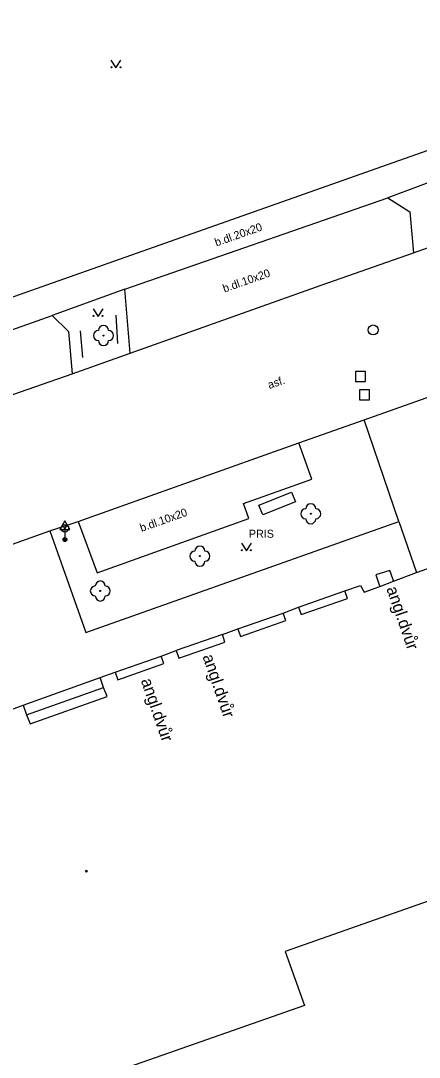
# Model space of a CAD drawing. Extents: x -599770 to -598493, y -1162076 to -1159209.
# Drawn here: x -599035.5 to -599015.6, y -1159443 to -1159391.2 of the extents above; entities that cross this region are included whole.
import ezdxf

# ---------------------------------------------------------------- set-up
doc = ezdxf.new("R2010")
doc.units = 0
doc.layers.add('Podklad', color=7, linetype='Continuous')

msp = doc.modelspace()

# ---------------------------------------------------------------- linework, layer by layer
at = {"layer": 'Podklad'}
for p, q in [((-599033.422, -1159416.73), (-599033.157, -1159416.465)), ((-599033.422, -1159416.465), (-599033.157, -1159416.73)), ((-599033.29, -1159416.651), (-599033.29, -1159417.16)), ((-599033.29, -1159416.785), (-599033.29, -1159417.16))]:
    msp.add_line(p, q, dxfattribs=at)
for points in [[(-599066.08, -1159415.71), (-599053.26, -1159411.13), (-599037.8, -1159405.7), (-598985.61, -1159387.27)], [(-599030.99, -1159393.215), (-599030.74, -1159393.59), (-599030.49, -1159393.215)], [(-599013.13, -1159398.59), (-599017.15, -1159400.09)], [(-599030.29, -1159404.65), (-599017.15, -1159400.09)], [(-599017.15, -1159400.09), (-599016.04, -1159400.78), (-599015.86, -1159402.84)], [(-599015.86, -1159402.84), (-599012.86, -1159401.77)], [(-599030.02, -1159407.85), (-599020.48, -1159404.45), (-599015.86, -1159402.84)], [(-599030.29, -1159404.65), (-599033.93, -1159405.97)], [(-599030.02, -1159407.85), (-599030.29, -1159404.65)], [(-599046.84, -1159410.54), (-599033.93, -1159405.97)], [(-599033.93, -1159405.97), (-599033.11, -1159406.77), (-599032.92, -1159408.88)], [(-599031.88, -1159405.635), (-599031.63, -1159406.01), (-599031.38, -1159405.635)], [(-599030.75, -1159405.95), (-599030.66, -1159407.36)], [(-599032.53, -1159406.74), (-599032.41, -1159408.06)], [(-599032.92, -1159408.88), (-599030.02, -1159407.85)], [(-599046.63, -1159413.65), (-599032.92, -1159408.88)], [(-599018.33, -1159411.18), (-599012.65, -1159409.16)], [(-599021.59, -1159412.32), (-599018.33, -1159411.18)], [(-599016.59, -1159416.26), (-599018.33, -1159411.18)], [(-599032.62, -1159416.26), (-599031.68, -1159418.82), (-599024.09, -1159416.11), (-599024.36, -1159415.36), (-599020.94, -1159414.15), (-599021.59, -1159412.32)], [(-599032.62, -1159416.26), (-599021.59, -1159412.32)], [(-599023.59, -1159415.44), (-599021.96, -1159414.79), (-599021.76, -1159415.28), (-599023.4, -1159415.93), (-599023.59, -1159415.44)], [(-599034.05, -1159416.73), (-599032.24, -1159421.81), (-599016.59, -1159416.26)], [(-599034.05, -1159416.73), (-599032.62, -1159416.26)], [(-599016.59, -1159416.26), (-599015.72, -1159418.81)], [(-599042.28, -1159419.66), (-599034.05, -1159416.73)], [(-599024.47, -1159417.345), (-599024.22, -1159417.72), (-599023.97, -1159417.345)], [(-599015.72, -1159418.81), (-599015.39, -1159418.69), (-599013.13, -1159417.84), (-599012.45, -1159417.59)], [(-599018.33, -1159419.79), (-599017.55, -1159419.5), (-599016.86, -1159419.24), (-599015.72, -1159418.81)], [(-599016.86, -1159419.24), (-599016.9, -1159419.13), (-599017.05, -1159418.7), (-599017.75, -1159418.93), (-599017.59, -1159419.38), (-599017.55, -1159419.5)], [(-599019.3, -1159419.72), (-599018.51, -1159419.46)], [(-599018.51, -1159419.46), (-599018.33, -1159419.79)], [(-599021.61, -1159420.53), (-599019.3, -1159419.72)], [(-599019.17, -1159420.1), (-599019.3, -1159419.72)], [(-599022.38, -1159420.83), (-599021.61, -1159420.53)], [(-599021.61, -1159420.53), (-599021.48, -1159420.91)], [(-599021.48, -1159420.91), (-599019.17, -1159420.1)], [(-599024.65, -1159421.62), (-599022.38, -1159420.83)], [(-599022.25, -1159421.21), (-599022.38, -1159420.83)], [(-599024.52, -1159422), (-599022.25, -1159421.21)], [(-599025.42, -1159421.9), (-599027.72, -1159422.7)], [(-599025.42, -1159421.9), (-599024.65, -1159421.62)], [(-599025.29, -1159422.28), (-599025.42, -1159421.9)], [(-599024.65, -1159421.62), (-599024.52, -1159422)], [(-599027.59, -1159423.08), (-599025.29, -1159422.28)], [(-599030.77, -1159423.79), (-599028.48, -1159422.98)], [(-599028.48, -1159422.98), (-599027.72, -1159422.7)], [(-599028.35, -1159423.36), (-599028.48, -1159422.98)], [(-599027.72, -1159422.7), (-599027.59, -1159423.08)], [(-599030.64, -1159424.17), (-599028.35, -1159423.36)], [(-599035.38, -1159425.43), (-599031.53, -1159424.06)], [(-599031.53, -1159424.06), (-599030.77, -1159423.79)], [(-599031.36, -1159424.55), (-599031.53, -1159424.06)], [(-599030.77, -1159423.79), (-599030.64, -1159424.17)], [(-599035.21, -1159425.92), (-599031.36, -1159424.55)], [(-599031.18, -1159425), (-599031.36, -1159424.55)], [(-599035.03, -1159426.37), (-599031.18, -1159425)], [(-599036.15, -1159425.72), (-599035.38, -1159425.43)], [(-599035.38, -1159425.43), (-599035.21, -1159425.92)], [(-599035.21, -1159425.92), (-599035.03, -1159426.37)], [(-599007.6, -1159432.58), (-599022.28, -1159437.74)], [(-599022.28, -1159437.74), (-599021.32, -1159440.44)], [(-599021.32, -1159440.44), (-599032.67, -1159444.42)]]:
    msp.add_lwpolyline(points, dxfattribs=at)
for points in [[(-599018.76, -1159409.27), (-599018.26, -1159409.27), (-599018.26, -1159408.77), (-599018.76, -1159408.77)], [(-599018.56, -1159410.18), (-599018.06, -1159410.18), (-599018.06, -1159409.68), (-599018.56, -1159409.68)], [(-599033.54, -1159416.651), (-599033.04, -1159416.651), (-599033.29, -1159416.218)]]:
    msp.add_lwpolyline(points, close=True, dxfattribs=at)
for centre, radius in [((-599030.965, -1159393.565), 0.025), ((-599030.515, -1159393.565), 0.025), ((-599031.855, -1159405.985), 0.025), ((-599031.405, -1159405.985), 0.025), ((-599017.88, -1159406.69), 0.25), ((-599031.36, -1159406.97), 0.025), ((-599021, -1159415.87), 0.025), ((-599033.29, -1159416.598), 0.188), ((-599033.29, -1159417.16), 0.1), ((-599033.29, -1159417.16), 0.0723), ((-599033.29, -1159417.16), 0.0438), ((-599026.54, -1159417.99), 0.025), ((-599024.445, -1159417.695), 0.025), ((-599023.995, -1159417.695), 0.025), ((-599031.52, -1159419.73), 0.025), ((-599032.22, -1159433.73), 0.045), ((-599032.22, -1159433.73), 0.0199)]:
    msp.add_circle(centre, radius, dxfattribs=at)
for centre, start, end in [((-599031.36, -1159406.72), 0, 180), ((-599031.61, -1159406.97), 90, 270), ((-599031.11, -1159406.97), 270, 90), ((-599031.36, -1159407.22), 180, 0), ((-599021, -1159415.62), 0, 180), ((-599021.25, -1159415.87), 90, 270), ((-599020.75, -1159415.87), 270, 90), ((-599021, -1159416.12), 180, 0), ((-599026.79, -1159417.99), 90, 270), ((-599026.54, -1159417.74), 0, 180), ((-599026.29, -1159417.99), 270, 90), ((-599026.54, -1159418.24), 180, 0), ((-599031.77, -1159419.73), 90, 270), ((-599031.52, -1159419.48), 0, 180), ((-599031.27, -1159419.73), 270, 90), ((-599031.52, -1159419.98), 180, 0)]:
    msp.add_arc(centre, 0.25, start, end, dxfattribs=at)

# ---------------------------------------------------------------- texts
for s, height, rotation, p in [('b.dl.20x20', 0.4, 19.3035, (-599025.72, -1159402.52)), ('b.dl.10x20', 0.4, 19.3035, (-599025.32, -1159404.82)), ('asf.', 0.4, 19, (-599023.07, -1159409.64)), ('b.dl.10x20', 0.4, 19.5159, (-599029.46, -1159416.78)), ('angl.dvůr', 0.6, 289.1291, (-599017.23, -1159419.61)), ('angl.dvůr', 0.6, 289.1291, (-599026.42, -1159423)), ('angl.dvůr', 0.6, 289.1291, (-599029.5, -1159424.2))]:
    msp.add_text(s, height=height, rotation=rotation, dxfattribs=at).set_placement(p)
msp.add_text('PRIS', height=0.4, dxfattribs=at).set_placement((-599024.09, -1159417.07))

doc.saveas('drawing.dxf')
